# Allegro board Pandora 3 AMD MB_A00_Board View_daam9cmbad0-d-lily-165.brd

Outline 291.55 x 153.75 mm; copper layers: TOP, SGND, IN1, SVCC, IN2, IN3, SGND1, IN4, SGND2, BOTTOM. Coordinates in mm from the lower left corner of the outline.

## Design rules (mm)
net group DFP-S4(4.5: nets M_A_CLK0 M_A_CLK0# M_A_CLK1 M_A_CLK1# M_B_CLK0 M_B_CLK0# M_B_CLK1 M_B_CLK1#
net group DFP-S4.5(7: nets SATA_RXN0 SATA_RXN0_C SATA_RXP0 SATA_RXP0_C SATA_TXN0 SATA_TXN0_C SATA_TXP0 SATA_TXP0_C USB2_N1_L USB2_N1_R USB2_P1_L USB2_P1_R USB2N0 USB2N1_BT USB2N1_BT_R USB2N2_CAM USB2N2_CAM_R USB2N3_CR USB2N3_CR_R USB2P0 USB2P1_BT USB2P1_BT_R USB2P2_CAM USB2P2_CAM_R USB2P3_CR USB2P3_CR_R USB3_RXN2 USB3_RXN2_C USB3_RXN2_L USB3_RXN2_RE USB3_RXP2 USB3_RXP2_C USB3_RXP2_L USB3_RXP2_RE USB3_TXN2 USB3_TXN2_C USB3_TXN2_L USB3_TXN2_R USB3_TXN2_RE USB3_TXP2 USB3_TXP2_C USB3_TXP2_L USB3_TXP2_R USB3_TXP2_RE USB3_USB2_N2 USB3_USB2_P2
net group DFP-S4W4.5(4: nets CLK_PCIE_LANN CLK_PCIE_LANN_R CLK_PCIE_LANP CLK_PCIE_LANP_R CLK_PCIE_WLANN CLK_PCIE_WLANN_R CLK_PCIE_WLANP CLK_PCIE_WLANP_R CLK_VGA_N CLK_VGA_N_R CLK_VGA_P CLK_VGA_P_R EDP_AUXN EDP_AUXP EDP_TXN0 EDP_TXN1 EDP_TXP0 EDP_TXP1 INT_HDMI_TXCN INT_HDMI_TXCP INT_HDMI_TXN0 INT_HDMI_TXN1 INT_HDMI_TXN2 INT_HDMI_TXP0 INT_HDMI_TXP1 INT_HDMI_TXP2 PCIE_RXN0_WLAN PCIE_RXN1_LAN PCIE_RXN1_LAN_C PCIE_RXP0_WLAN PCIE_RXP1_LAN PCIE_RXP1_LAN_C PCIE_TXN0_WLAN PCIE_TXN0_WLAN_C PCIE_TXN1_LAN PCIE_TXN1_LAN_C PCIE_TXP0_WLAN PCIE_TXP0_WLAN_C PCIE_TXP1_LAN PCIE_TXP1_LAN_C PEG_RXN0 PEG_RXN0_C PEG_RXN1 PEG_RXN1_C PEG_RXN2 PEG_RXN2_C PEG_RXN3 PEG_RXN3_C PEG_RXN4 PEG_RXN4_C PEG_RXN5 PEG_RXN5_C PEG_RXN6 PEG_RXN6_C PEG_RXN7 PEG_RXN7_C PEG_RXP0 PEG_RXP0_C PEG_RXP1 PEG_RXP1_C PEG_RXP2 PEG_RXP2_C PEG_RXP3 PEG_RXP3_C PEG_RXP4 PEG_RXP4_C PEG_RXP5 PEG_RXP5_C PEG_RXP6 PEG_RXP6_C PEG_RXP7 PEG_RXP7_C PEG_TXN0_C PEG_TXN1_C PEG_TXN2 PEG_TXN2_C PEG_TXN3_C PEG_TXN4_C PEG_TXN5_C PEG_TXN6 PEG_TXN6_C PEG_TXN7_C PEG_TXP0_C PEG_TXP1_C PEG_TXP2 PEG_TXP2_C PEG_TXP3_C PEG_TXP4_C PEG_TXP5_C PEG_TXP6 PEG_TXP6_C PEG_TXP7_C SATA_RXN1 SATA_RXN1_C SATA_RXP1 SATA_RXP1_C SATA_TXN1 SATA_TXN1_C SATA_TXP1 SATA_TXP1_C USB3_RXN0 USB3_RXN0_C USB3_RXN0_L USB3_RXN1 USB3_RXN1_C USB3_RXN1_L USB3_RXP0 USB3_RXP0_C USB3_RXP0_L USB3_RXP1 USB3_RXP1_C USB3_RXP1_L USB3_TXN0 USB3_TXN0_C USB3_TXN0_L USB3_TXN0_RE USB3_TXN1 USB3_TXN1_C USB3_TXN1_L USB3_TXN1_RE USB3_TXP0 USB3_TXP0_C USB3_TXP0_L USB3_TXP0_RE USB3_TXP1 USB3_TXP1_C USB3_TXP1_L USB3_TXP1_RE USB3_USB2_N0 USB3_USB2_N1 USB3_USB2_P0 USB3_USB2_P1
net group DFP-S4W4.5-TB: nets EDP_AUXN_C EDP_AUXP_C EDP_TXN0_C EDP_TXN0_R EDP_TXN1_C EDP_TXN1_R EDP_TXP0_C EDP_TXP0_R EDP_TXP1_C EDP_TXP1_R HDMI_CLK+ HDMI_CLK- HDMI_TX0+ HDMI_TX0- HDMI_TX1+ HDMI_TX1- HDMI_TX2+ HDMI_TX2-
net group DFP-S4W5(4.5: nets M_A_DQS0 M_A_DQS1 M_A_DQS2 M_A_DQS3 M_A_DQS4 M_A_DQS5 M_A_DQS6 M_A_DQS7 M_A_DQS#0 M_A_DQS#1 M_A_DQS#2 M_A_DQS#3 M_A_DQS#4 M_A_DQS#5 M_A_DQS#6 M_A_DQS#7 M_B_DQS0 M_B_DQS1 M_B_DQS2 M_B_DQS3 M_B_DQS4 M_B_DQS5 M_B_DQS6 M_B_DQS7 M_B_DQS#0 M_B_DQS#1 M_B_DQS#2 M_B_DQS#3 M_B_DQS#4 M_B_DQS#5 M_B_DQS#6 M_B_DQS#7 WCKA0_0 WCKA0B_0 WCKA1_0 WCKA1B_0 WCKB1_1 WCKB1B_1
net group DFP-S8(7.5: nets LAN_MX0+ LAN_MX0- LAN_MX1+ LAN_MX1- LAN_MX2+ LAN_MX2- LAN_MX3+ LAN_MX3- MDI0+ MDI0- MDI1+ MDI1- MDI2- MDI3+ MDI3-
net group DFP-S8W4-TB: nets HDMI_CLK+_C HDMI_CLK+_R HDMI_CLK-_C HDMI_CLK-_R HDMI_TX0+_C HDMI_TX0+_R HDMI_TX0-_C HDMI_TX0-_R HDMI_TX1+_C HDMI_TX1+_R HDMI_TX1-_C HDMI_TX1-_R HDMI_TX2+_C HDMI_TX2+_R HDMI_TX2-_C HDMI_TX2-_R
net group DFP-S20W4.5-TB: nets 32K_X1 32K_X2 LAN_XTALO SI_XTALOUT XTALIN XTALOUT
net group W4.5(3.5: nets ACZ_BCLK_R ACZ_RST#_R ACZ_SDIN1 ACZ_SDIN2 ACZ_SDOUT_R ACZ_SPKR ACZ_SPKR_R ACZ_SYNC_R APU_PROCHOT#_R APU_PWRGD APU_SIC APU_SID APU_SPI_CLK APU_SPI_CS0# APU_SPI_HOLD# APU_SPI_SI APU_SPI_SO APU_SPI_WP BIOS_CS#_B BIOS_HOLD#_B BIOS_RD#_B BIOS_SPI_CLK_B BIOS_WP_B BIOS_WR#_B CLKRUN# CORE_PWM_PROCHOT# DGPUT_CLK DGPUT_CLK_R DGPUT_DATA DGPUT_DATA_R DMIC_CLK DMIC_CLK_C DMIC_CLK_R DMIC_DATA DMIC_DATA_C DMIC_DATA_R DP_AUX_ZVSS DP_ZVSS EC_SPI_CS# EC_SPI_DIN EC_SPI_DO EC_SPI_HOLD# EC_SPI_SCK EC_SPI_WP# GPIO_8_ROMSO GPIO_9_ROMSI GPIO_10_ROMSCK GPIO_22_ROMCSB HDA_BITCLK HDA_BITCLK_R HDA_RST# HDA_SDIN0 HDA_SDOUT HDA_SYNC HDMI_SCL HDMI_SCL_SNK HDMI_SDA HDMI_SDA_SNK I2C_SCL1 I2C_SCL_TP I2C_SDA1 I2C_SDA_TP LAD0 LAD0_R LAD1 LAD1_R LAD2 LAD2_R LAD3 LAD3_R LFRAME# LPC_LFRAME#_R ROMCSB ROMSCK ROMSI ROMSO SD_CD# SD_CLK SD_CMD SD_D0 SD_D1 SD_D2 SD_D3 SD_WP SERIRQ SMB_ALW_CLK SMB_ALW_DAT SMB_RUN_CLK SMB_RUN_DAT SMBCLK1 SMBCLK3 SMBDAT1 SMBDAT3
net group W4.5-TB: nets SL_CLK_100M
net group W5.5(4.5: nets ADBIA0 ADBIA1 ADBIB0 ADBIB1 CASA0B CASA1B CASB0B CASB1B CKEA0 CKEA1 CKEB0 CKEB1 CSA0B_0 CSA1B_0 CSB0B_0 CSB1B_0 DDBIA0_0 DDBIA0_1 DDBIA0_2 DDBIA0_3 DDBIA1_0 DDBIA1_1 DDBIA1_2 DDBIA1_3 DDBIB0_0 DDBIB0_1 DDBIB0_2 DDBIB0_3 DDBIB1_0 DDBIB1_1 DDBIB1_2 DDBIB1_3 DQA0_0 DQA0_1 DQA0_2 DQA0_3 DQA0_4 DQA0_5 DQA0_6 DQA0_7 DQA0_8 DQA0_9 DQA0_10 DQA0_11 DQA0_12 DQA0_13 DQA0_14 DQA0_15 DQA0_16 DQA0_17 DQA0_18 DQA0_19 DQA0_20 DQA0_21 DQA0_22 DQA0_23 DQA0_24 DQA0_25 DQA0_26 DQA0_27 DQA0_28 DQA0_29 DQA0_30 DQA0_31 DQA1_0 DQA1_1 DQA1_2 DQA1_3 DQA1_4 DQA1_5 DQA1_6 DQA1_7 DQA1_8 DQA1_9 DQA1_10 DQA1_11 DQA1_12 DQA1_13 DQA1_14 DQA1_15 DQA1_16 DQA1_17 DQA1_18 DQA1_19 DQA1_20 DQA1_21 DQA1_22 DQA1_23 DQA1_24 DQA1_25 DQA1_26 DQA1_27 DQA1_28 DQA1_29 DQA1_30 DQA1_31 DQB0_0 DQB0_1 DQB0_2 DQB0_3 DQB0_4 DQB0_5 DQB0_6 DQB0_7 DQB0_8 DQB0_9 DQB0_10 DQB0_11 DQB0_12 DQB0_13 DQB0_14 DQB0_15 DQB0_16 DQB0_17 DQB0_18 DQB0_19 DQB0_20 DQB0_21 DQB0_22 DQB0_23 DQB0_24 DQB0_25 DQB0_26 DQB0_27 DQB0_28 DQB0_29 DQB0_30 DQB0_31 DQB1_0 DQB1_1 DQB1_2 DQB1_3 DQB1_4 DQB1_5 DQB1_6 DQB1_7 DQB1_8 DQB1_9 DQB1_10 DQB1_11 DQB1_12 DQB1_13 DQB1_14 DQB1_15 DQB1_16 DQB1_17 DQB1_18 DQB1_19 DQB1_20 DQB1_21 DQB1_22 DQB1_23 DQB1_24 DQB1_25 DQB1_26 DQB1_27 DQB1_28 DQB1_29 DQB1_30 DQB1_31 EDCA0_0 EDCA0_1 EDCA0_2 EDCA0_3 EDCA1_0 EDCA1_1 EDCA1_2 EDCA1_3 EDCB0_0 EDCB0_1 EDCB0_2 EDCB0_3 EDCB1_0 EDCB1_1 EDCB1_2 EDCB1_3 MAA0_0 MAA0_1 MAA0_2 MAA0_3 MAA0_4 MAA0_5 MAA0_6 MAA0_7 MAA0_8 MAA1_0 MAA1_1 MAA1_2 MAA1_3 MAA1_4 MAA1_5 MAA1_6 MAA1_7 MAA1_8 MAB0_0 MAB0_1 MAB0_2 MAB0_3 MAB0_4 MAB0_5 MAB0_6 MAB0_7 MAB0_8 MAB1_0 MAB1_1 MAB1_2 MAB1_3 MAB1_4 MAB1_5 MAB1_6 MAB1_7 MAB1_8 RASA0B RASA1B RASB0B RASB1B WEA0B WEA1B WEB0B WEB1B
net group W7(5: nets M_A_A0 M_A_A1 M_A_A2 M_A_A3 M_A_A4 M_A_A5 M_A_A6 M_A_A7 M_A_A8 M_A_A9 M_A_A10 M_A_A11 M_A_A12 M_A_A13 M_A_BS#0 M_A_BS#1 M_A_CAS# M_A_CKE0 M_A_CKE1 M_A_DM0 M_A_DM1 M_A_DM2 M_A_DM3 M_A_DM4 M_A_DM5 M_A_DM6 M_A_DM7 M_A_DQ0 M_A_DQ1 M_A_DQ2 M_A_DQ3 M_A_DQ4 M_A_DQ5 M_A_DQ6 M_A_DQ7 M_A_DQ8 M_A_DQ9 M_A_DQ10 M_A_DQ11 M_A_DQ12 M_A_DQ13 M_A_DQ14 M_A_DQ15 M_A_DQ16 M_A_DQ17 M_A_DQ18 M_A_DQ19 M_A_DQ20 M_A_DQ21 M_A_DQ22 M_A_DQ23 M_A_DQ24 M_A_DQ25 M_A_DQ26 M_A_DQ27 M_A_DQ28 M_A_DQ29 M_A_DQ30 M_A_DQ31 M_A_DQ32 M_A_DQ33 M_A_DQ34 M_A_DQ35 M_A_DQ36 M_A_DQ37 M_A_DQ38 M_A_DQ39 M_A_DQ40 M_A_DQ41 M_A_DQ42 M_A_DQ43 M_A_DQ44 M_A_DQ45 M_A_DQ46 M_A_DQ47 M_A_DQ48 M_A_DQ49 M_A_DQ50 M_A_DQ51 M_A_DQ52 M_A_DQ53 M_A_DQ54 M_A_DQ55 M_A_DQ56 M_A_DQ57 M_A_DQ58 M_A_DQ59 M_A_DQ60 M_A_DQ61 M_A_DQ62 M_A_DQ63 M_A_EVENT# M_A_ODT0 M_A_ODT1 M_A_RAS# M_A_RESET# M_A_WE# M_B0_ODT0 M_B0_ODT1 M_B_A0 M_B_A1 M_B_A2 M_B_A3 M_B_A4 M_B_A5 M_B_A6 M_B_A7 M_B_A8 M_B_A9 M_B_A10 M_B_A11 M_B_A12 M_B_A13 M_B_BS#0 M_B_BS#1 M_B_CAS# M_B_CKE0 M_B_CKE1 M_B_DM0 M_B_DM1 M_B_DM2 M_B_DM3 M_B_DM4 M_B_DM5 M_B_DM6 M_B_DM7 M_B_DQ0 M_B_DQ1 M_B_DQ2 M_B_DQ3 M_B_DQ4 M_B_DQ5 M_B_DQ6 M_B_DQ7 M_B_DQ8 M_B_DQ9 M_B_DQ10 M_B_DQ11 M_B_DQ12 M_B_DQ13 M_B_DQ14 M_B_DQ15 M_B_DQ16 M_B_DQ17 M_B_DQ18 M_B_DQ19 M_B_DQ20 M_B_DQ21 M_B_DQ22 M_B_DQ23 M_B_DQ24 M_B_DQ25 M_B_DQ26 M_B_DQ27 M_B_DQ28 M_B_DQ29 M_B_DQ30 M_B_DQ31 M_B_DQ32 M_B_DQ33 M_B_DQ34 M_B_DQ35 M_B_DQ36 M_B_DQ37 M_B_DQ38 M_B_DQ39 M_B_DQ40 M_B_DQ41 M_B_DQ42 M_B_DQ43 M_B_DQ44 M_B_DQ45 M_B_DQ46 M_B_DQ47 M_B_DQ48 M_B_DQ49 M_B_DQ50 M_B_DQ51 M_B_DQ52 M_B_DQ53 M_B_DQ54 M_B_DQ55 M_B_DQ56 M_B_DQ57 M_B_DQ58 M_B_DQ59 M_B_DQ60 M_B_DQ61 M_B_DQ62 M_B_DQ63 M_B_EVENT# M_B_RAS# M_B_RESET# M_B_WE# M_MA_BG0 M_MA_BG1 M_MB_BG0 M_MB_BG1 MEM_MA_ACT# MEM_MB_ACT#
net group W10-T1234B: nets 62771_SVC 62771_SVC_GFX 62771_SVD 62771_SVD_GFX 62771_SVT 62771_SVT_GFX APU_SVC APU_SVD APU_SVT GFX_SVC GFX_SVC_R GFX_SVD GFX_SVD_R GFX_SVT P_ZVDDP_P_TX_095 P_ZVSS_P_RX_095 SVC SVD
net group W40-T1234B: nets AUD_SPK_L+ AUD_SPK_L- AUD_SPK_R+ AUD_SPK_R-

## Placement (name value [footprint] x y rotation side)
C8  0.22U/10V_4  [C0402]  62.94 124.59 90 bottom
C9  0.22U/10V_4  [C0402]  61.98 124.59 90 bottom
C10  0.22U/10V_4  [C0402]  60.31 122.45 90 bottom
C11  0.22U/10V_4  [C0402]  61.32 122.45 90 bottom
C12  0.22U/10V_4  [C0402]  58.51 123.12 180 bottom
C13  0.22U/10V_4  [C0402]  58.51 124.13 180 bottom
C14  0.22U/10V_4  [C0402]  54.7 122.35 180 bottom
C15  0.22U/10V_4  [C0402]  54.7 123.37 180 bottom
C16  0.22U/10V_4  [C0402]  50.91 123.42 180 bottom
C17  0.22U/10V_4  [C0402]  50.91 122.41 180 bottom
C18  0.22U/10V_4  [C0402]  50.89 120.25 180 bottom
C19  0.22U/10V_4  [C0402]  50.89 121.27 180 bottom
C20  0.22U/10V_4  [C0402]  50.87 119.12 180 bottom
C21  0.22U/10V_4  [C0402]  50.87 118.11 180 bottom
C22  0.22U/10V_4  [C0402]  50.86 117.13 180 bottom
C23  0.22U/10V_4  [C0402]  50.86 116.17 180 bottom
C199  *MLVG04021R0UV18BP_NC  [C0402]  268.42 108.01 270 top
C215  *MLVG04021R0UV18BP_NC  [C0402]  268.42 106.29 90 top
C225  *2200P/50V_4_NC  [C0402]  69.44 102.58 180 top
C228  0.1U/16V/X7R_4  [C0402]  267.9 104.95 0 top
C254  *MLVG04021R0UV18BP_NC  [C0402]  268.42 103.61 270 top
C287  *MLVG04021R0UV18BP_NC  [C0402]  268.42 101.58 90 top
C302  *MLVG04021R0UV18BP_NC  [C0402]  267.4 99.55 270 top
C310  *MLVG04021R0UV18BP_NC  [C0402]  267.4 97.52 90 top
C323  *MLVG04021R0UV18BP_NC  [C0402]  268.42 95.48 270 top
C334  4.7U/6.3V_6  [C0603]  38.67 91.9 180 top
C336  *MLVG04021R0UV18BP_NC  [C0402]  267.4 93.45 90 top
C339  0.1U/16V/X7R_4  [C0402]  38.57 90.48 0 top
C341  *4.7U/6.3V_6_NC  [C0603]  276.01 91.72 180 top
C343  0.1U/16V/X7R_4  [C0402]  273.22 88.93 0 bottom
C345  10P/50V_4  [C0402]  275.4 89.03 270 top
C347  10P/50V_4  [C0402]  275.4 87.2 90 top
C352  0.1U/16V/X7R_4  [C0402]  274.64 84.82 0 top
C356  0.1U/16V/X7R_4  [C0402]  271.56 86.42 90 bottom
C357  1U/6.3V_4  [C0402]  270.52 86.42 90 bottom
C359  *4.7U/6.3V_6_NC  [C0603]  272.76 90.73 90 bottom
C360  *0.1U/16V/X7R_4_NC  [C0402]  275.76 81.97 0 top
C370  0.1U/16V/X7R_4  [C0402]  173.5 80.53 180 top
C371  4.7U/6.3V_6  [C0603]  172.63 79.3 0 top
C391  0.1U/16V/X7R_4  [C0402]  276.57 70.11 90 top
C413  0.01U/50V/X7R_4  [C0402]  266.82 65.45 270 top
C414  0.1U/16V/X7R_4  [C0402]  265.93 64.11 180 top
C415  0.01U/50V/X7R_4  [C0402]  275.56 64.83 90 top
C418  0.1U/16V/X7R_4  [C0402]  267.7 61.47 270 top
C419  0.1U/16V/X7R_4  [C0402]  268.72 61.47 270 top
C420  0.1U/16V/X7R_4  [C0402]  269.81 61.47 270 top
C421  0.1U/16V/X7R_4  [C0402]  270.82 61.47 270 top
C422  0.1U/16V/X7R_4  [C0402]  271.84 61.47 270 top
C423  0.1U/16V/X7R_4  [C0402]  272.86 61.47 270 top
C424  0.1U/16V/X7R_4  [C0402]  273.87 61.47 270 top
C425  0.1U/16V/X7R_4  [C0402]  274.89 61.47 270 top
C458  0.1U/16V/X7R_4  [C0402]  173.38 52.3 180 top
C459  0.1U/16V/X7R_4  [C0402]  171.87 53.7 270 top
C463  0.1U/25V_6  [C0603]  182.82 51.67 270 top
C464  0.1U/25V_6  [C0603]  184.34 51.67 270 top
C478  0.01U/50V/X7R_4  [C0402]  168.49 49.34 0 top
C479  0.1U/16V/X7R_4  [C0402]  170.46 49.32 180 top
C481  10U/6.3V_6  [C0603]  273.09 46.89 90 top
C482  0.1U/16V/X7R_4  [C0402]  271.9 46.94 90 top
C483  150P/50V_4  [C0402]  270.94 46.94 90 top
C485  1U/25V_6  [C0603]  179.64 43.79 0 top
C486  *0.1U/16V/X7R_4_NC  [C0402]  184.98 43.92 180 top
C487  *100P/50V_4_NC  [C0402]  270.37 43.64 0 top
C489  0.1U/25V_6  [C0603]  183.05 42.93 90 top
C490  *100P/50V_4_NC  [C0402]  270.34 42.07 0 top
C496  *4.7U/6.3V_6_NC  [C0603]  263.06 41.84 180 top
C497  0.1U/16V/X7R_4  [C0402]  263 43.03 180 top
C502  0.1U/16V/X7R_4  [C0402]  106.79 36.4 180 top
C503  0.1U/16V/X7R_4  [C0402]  171.51 35.67 270 top
C504  0.1U/16V/X7R_4  [C0402]  172.53 35.67 270 top
C509  0.1U/16V_4  [C0402]  171.64 34.24 0 bottom
C512  0.1U/16V/X7R_4  [C0402]  13.11 29.36 90 top
C513  1U/6.3V_4  [C0402]  14.1 29.36 90 top
C517  0.1U/16V/X7R_4  [C0402]  250.47 25.46 180 top
C526  0.047U/10V_4  [C0402]  6.52 18.42 180 top
C529  0.1U/16V/X7R_4  [C0402]  5.96 4.2 180 top
C530  0.1U/16V/X7R_4  [C0402]  25.57 3.29 90 top
C531  1U/6.3V_4  [C0402]  24.45 3.29 90 top
C533  0.047U/10V_4  [C0402]  5.96 3.1 180 top
C573  0.1U/16V/X7R_4  [C0402]  42.86 110.34 180 top
C574  2200P/50V_4  [C0402]  43.5 113.77 180 bottom
C593  1000P/3KV_18  [CC1808]  277.43 110.98 0 bottom
C623  0.1U/25V_6  [C0603]  104.76 15.58 270 bottom
C624  *0.1U/16V/X7R_4_NC  [C0402]  271.5 83.15 270 top
C625  0.1U/16V/X7R_4  [C0402]  271.16 90.45 90 bottom
C626  0.1U/16V/X7R_4  [C0402]  270.12 90.45 90 bottom
C627  0.1U/16V/X7R_4  [C0402]  275.04 90.53 180 top
C628  0.1U/16V/X7R_4  [C0402]  268.77 89.64 0 bottom
C632  *4.7U/6.3V_6_NC  [C0603]  268.67 88.17 0 bottom
C634  0.1U/16V_4  [C0402]  272.66 82.61 180 bottom
C635  *4.7U/6.3V_6_NC  [C0603]  272.68 83.27 90 top
C638  1U/6.3V_4  [C0402]  272.71 80.35 180 bottom
C642  0.1U/16V/X7R_4  [C0402]  267.16 74.55 270 top
C643  0.1U/16V/X7R_4  [C0402]  268.18 74.55 270 top
C645  0.1U/16V/X7R_4  [C0402]  273.22 87.94 0 bottom
C648  0.01U/50V/X7R_4  [C0402]  277.74 82.91 90 bottom
C659  0.01U/50V/X7R_4  [C0402]  268.5 70.7 90 top
C660  1U/6.3V_4  [C0402]  265.93 63.15 0 top
C661  0.1U/16V/X7R_4  [C0402]  275.07 68.94 270 top
C662  0.1U/16V/X7R_4  [C0402]  275.08 70.7 90 top
C663  0.1U/16V/X7R_4  [C0402]  267.54 70.98 90 top
C664  0.1U/16V/X7R_4  [C0402]  276.83 63.31 90 top
C665  0.1U/25V_6  [C0603]  103.32 15.58 270 bottom
C666  0.1U/16V/X7R_4  [C0402]  175.96 57.76 270 bottom
C667  0.1U/16V/X7R_4  [C0402]  176.98 57.76 270 bottom
C668  0.1U/16V/X7R_4  [C0402]  178.25 57.76 270 bottom
C669  0.1U/16V/X7R_4  [C0402]  179.26 57.76 270 bottom
C674  0.1U/16V/X7R_4  [C0402]  172.89 53.7 270 top
C675  0.1U/16V/X7R_4  [C0402]  173.67 54.08 270 bottom
C676  0.1U/16V/X7R_4  [C0402]  174.82 54.08 270 bottom
C681  0.047U/25V_4  [C0402]  264.99 55.99 90 bottom
C682  0.1U/25V_6  [C0603]  101.13 16.16 0 bottom
C684  *10U/6.3V_6_NC  [C0603]  263 46.89 0 top
C688  *100P/50V_4_NC  [C0402]  268.49 41.3 180 top
C689  0.022U/25V_4  [C0402]  177.51 36.35 270 bottom
C690  0.1U/25V_6  [C0603]  83.5 5.44 90 bottom
C691  0.1U/16V/X7R_4  [C0402]  236.97 24.42 180 bottom
C692  0.1U/16V_4  [C0402]  194.5 30.08 180 bottom
C694  10U/6.3V_6  [C0603]  194.76 28.81 0 bottom
C700  0.1U/16V/X7R_4  [C0402]  5.75 25.13 270 bottom
C701  4.7U/6.3V_6  [C0603]  4.48 25.13 270 bottom
C703  *68P/50V_4_NC  [C0402]  194.5 25.25 180 bottom
C712  0.1U/16V/X7R_4  [C0402]  230.82 19.64 180 bottom
C714  *0.1U/16V/X7R_4_NC  [C0402]  224.7 17.45 90 bottom
C716  *0.1U/16V/X7R_4_NC  [C0402]  230.32 18.09 270 bottom
C723  10U/6.3V_6  [C0603]  194.88 15.6 0 bottom
C724  0.1U/16V/X7R_4  [C0402]  57.59 16.57 270 bottom
C725  0.01U/50V/X7R_4  [C0402]  232.86 14.71 0 bottom
C728  0.1U/16V/X7R_4  [C0402]  224.98 14.08 90 bottom
C729  0.1U/16V_4  [C0402]  194.63 14.33 180 bottom
C730  0.1U/16V_4  [C0402]  194.63 13.19 180 bottom
C733  0.1U/16V_4  [C0402]  194.63 12.04 180 bottom
C734  0.1U/16V/X7R_4  [C0402]  29.91 9.76 180 bottom
C735  4.7U/6.3V_6  [C0603]  27.12 11.28 0 bottom
C739  0.01U/50V/X7R_4  [C0402]  33.21 9.94 270 bottom
C740  0.01U/50V/X7R_4  [C0402]  34.3 9.94 270 bottom
C741  0.01U/50V/X7R_4  [C0402]  35.32 9.94 270 bottom
C742  0.01U/50V/X7R_4  [C0402]  36.46 9.94 270 bottom
C743  *22U/6.3V_6_NC  [C0603]  30.42 11.28 180 bottom
C744  4.7U/6.3V_6  [C0603]  27.12 9.76 0 bottom
C745  0.1U/16V/X7R_4  [C0402]  21.84 8.03 0 bottom
C746  0.1U/16V/X7R_4  [C0402]  20.41 6.9 90 bottom
C747  0.1U/25V_6  [C0603]  150.25 31.6 180 bottom
C748  0.1U/25V_6  [C0603]  150.25 33.13 180 bottom
C749  0.1U/16V_4  [C0402]  63.9 124.59 270 bottom
C750  0.1U/16V_4  [C0402]  64.86 124.59 270 bottom
C751  *150P/50V_4_NC  [C0402]  57.27 104.81 180 top
C752  *150P/50V_4_NC  [C0402]  50.86 102.46 0 bottom
C753  0.1U/16V_4  [C0402]  51.96 22.89 270 top
C754  0.01u/50V_4  [C0402]  38.8 25 180 top
C755  *0.01U/50V_4_NC  [C0402]  51.5 26.14 180 top
C756  0.01u/50V_4  [C0402]  49.47 20.66 0 top
C757  150P/50V_4  [C0402]  97.98 109.68 0 bottom
C758  150P/50V_4  [C0402]  103.94 104.86 90 top
C759  *0.1u/16V_4_NC  [C0402]  102.92 104.86 270 top
C760  0.1U/16V_4  [C0402]  99.68 112.13 180 top
C761  *100P/50V_4_NC  [C0402]  80.73 120.93 90 bottom
C762  18P/50V_4  [C0402]  103.46 116.89 180 top
C763  18P/50V_4  [C0402]  100.02 116.89 0 top
C764  *0.22U/10V_4_NC  [C0402]  88.33 124.9 180 bottom
C766  4.7P/50V_4  [C0402]  68.88 121.52 180 bottom
C767  4.7P/50V_4  [C0402]  67.16 121.52 180 bottom
C768  10P/50V_4  [C0402]  102.81 107.27 0 bottom
C769  *10P/50V_4_NC  [C0402]  102.68 108.67 0 bottom
C770  *0.1u/16V_4_NC  [C0402]  123.89 144.51 0 top
C771  22U/6.3V/X5R_6  [C0603]  83.48 91.5 180 top
C772  22U/6.3V/X5R_6  [C0603]  83.48 90.09 180 top
C773  22U/6.3V/X5R_6  [C0603]  65.35 91.42 180 top
C774  22U/6.3V/X5R_6  [C0603]  80.97 91.98 270 top
C775  22U/6.3V/X5R_6  [C0603]  70.29 90.25 270 top
C776  47U/4V/X5R_6  [C0603]  77.05 99.09 90 top
C777  22U/6.3V/X5R_6  [C0603]  69.79 98.25 0 top
C779  22U/6.3V/X5R_6  [C0603]  80.33 132.75 270 bottom
C782  0.22U/10V_4  [C0402]  71.3 96.4 270 top
C783  0.22U/10V_4  [C0402]  64.75 94.26 0 top
C784  0.22U/10V_4  [C0402]  65.12 92.64 180 top
C785  22U/6.3V/X5R_6  [C0603]  62.53 93.38 0 top
C786  22U/6.3V/X5R_6  [C0603]  62.5 95.86 0 top
C787  22U/6.3V/X5R_6  [C0603]  75.86 92.25 180 top
C788  22U/6.3V/X5R_6  [C0603]  75.86 90.84 180 top
C789  22U/6.3V/X5R_6  [C0603]  78.51 90.63 0 top
C790  22U/6.3V/X5R_6  [C0603]  66.89 89.29 0 top
C792  47U/4V/X5R_6  [C0603]  70.3 108.72 0 top
C793  47U/4V/X5R_6  [C0603]  70.3 107.16 0 top
C798  0.22U/10V_4  [C0402]  68.15 90.85 270 top
C799  0.22U/10V_4  [C0402]  63.18 91.43 0 top
C800  0.22U/10V_4  [C0402]  67.19 90.85 270 top
C801  180P/50V_4  [C0402]  67.65 93.42 90 top
C802  0.22U/10V_4  [C0402]  71.1 102.2 270 top
C803  0.22U/10V_4  [C0402]  75.49 109.23 180 top
C804  0.22U/10V_4  [C0402]  70.05 111.45 270 top
C805  0.22U/10V_4  [C0402]  71.37 113.18 270 top
C806  0.22U/10V_4  [C0402]  72.62 110.96 90 top
C807  0.22U/10V_4  [C0402]  72.9 109.4 0 top
C808  0.22U/10V_4  [C0402]  69.44 101.62 0 top
C809  0.22U/10V_4  [C0402]  77.37 111.62 90 top
C810  180P/50V_4  [C0402]  79.59 111.68 90 top
C811  0.22U/10V_4  [C0402]  71.5 89.97 270 top
C812  0.22U/10V_4  [C0402]  69.11 90.92 270 top
C813  0.22U/10V_4  [C0402]  71.37 92.79 90 top
C814  0.22U/10V_4  [C0402]  74.16 94.2 0 top
C815  180P/50V_4  [C0402]  71.96 91.38 0 top
C816  180P/50V_4  [C0402]  79.53 92.19 270 top
C817  10U/6.3V_4  [C0402]  101.91 102.04 0 top
C818  0.22U/10V_4  [C0402]  101.91 103.05 0 top
C819  10U/6.3V_4  [C0402]  99 100.69 270 top
C820  10U/6.3V_4  [C0402]  104.33 98.79 90 top
C821  10U/6.3V_4  [C0402]  84.29 101.1 0 top
C822  10U/6.3V_4  [C0402]  86.55 101.05 180 top
C823  0.22U/10V_4  [C0402]  102.3 98.79 90 top
C824  0.22U/10V_4  [C0402]  100.14 100.69 270 top
C825  0.22U/10V_4  [C0402]  101.28 100.69 270 top
C826  0.22U/10V_4  [C0402]  103.32 98.79 90 top
C827  0.22U/10V_4  [C0402]  99 98.79 90 top
C828  0.22U/10V_4  [C0402]  100.14 98.79 90 top
C829  180P/50V_4  [C0402]  101.28 98.79 90 top
C830  1U/6.3V_4  [C0402]  89.69 100.77 90 top
C831  1U/6.3V_4  [C0402]  87.32 99.86 180 top
C832  1U/6.3V_4  [C0402]  88.73 100.77 90 top
C833  22U/6.3V/X5R_6  [C0603]  55.88 103.5 0 top
C834  22U/6.3V/X5R_6  [C0603]  56.11 110.9 0 top
C835  22U/6.3V/X5R_6  [C0603]  64.24 115.31 180 top
C836  22U/6.3V/X5R_6  [C0603]  63.16 107.5 270 top
C837  22U/6.3V/X5R_6  [C0603]  60.91 108.89 90 top
C838  22U/6.3V/X5R_6  [C0603]  63.16 102.21 270 top
C839  22U/6.3V/X5R_6  [C0603]  63.16 104.88 90 top
C840  22U/6.3V/X5R_6  [C0603]  60.74 115.31 0 top
C841  22U/6.3V/X5R_6  [C0603]  63.83 111.89 270 top
C842  10U/6.3V_4  [C0402]  85.83 108.41 270 top
C843  10U/6.3V_4  [C0402]  86.84 108.41 270 top
C844  0.22U/10V_4  [C0402]  84.81 108.41 270 top
C845  0.22U/10V_4  [C0402]  58.99 104.77 0 top
C846  0.22U/10V_4  [C0402]  62.13 99.95 90 top
C847  0.22U/10V_4  [C0402]  65.28 112.03 270 top
C848  0.22U/10V_4  [C0402]  61.64 113.49 270 top
C849  0.22U/10V_4  [C0402]  63.38 99.92 90 top
C850  0.22U/10V_4  [C0402]  66.53 112.1 270 top
C851  0.22U/10V_4  [C0402]  55.65 99.88 90 top
C852  0.22U/10V_4  [C0402]  57.77 100.31 90 top
C853  0.22U/10V_4  [C0402]  59.3 105.76 0 top
C854  180P/50V_4  [C0402]  68.23 110.44 180 top
C860  22U/6.3V/X5R_6  [C0603]  96.84 125.64 0 bottom
C862  22U/6.3V/X5R_6  [C0603]  96.84 127.05 0 bottom
C863  47U/4V/X5R_6  [C0603]  79.36 105.14 0 top
C864  0.22U/10V_4  [C0402]  78.62 98.93 0 top
C865  0.22U/10V_4  [C0402]  79.87 108.62 270 top
C866  0.22U/10V_4  [C0402]  78.59 101.99 90 top
C867  0.22U/10V_4  [C0402]  79.57 100.27 90 top
C868  0.22U/10V_4  [C0402]  78.61 100.27 90 top
C869  0.22U/10V_4  [C0402]  82.23 100.28 90 top
C870  0.22U/10V_4  [C0402]  78.62 97.97 0 top
C871  0.22U/10V_4  [C0402]  81.72 102.24 270 top
C872  180P/50V_4  [C0402]  79.57 101.99 90 top
C873  0.22U/10V_4  [C0402]  83.32 102.48 90 top
C874  10U/6.3V_4  [C0402]  241.72 9.48 90 top
C875  1U/6.3V_4  [C0402]  105.44 108.43 90 top
C876  0.1U/16V_4  [C0402]  243.9 6.66 0 top
C877  1U/6.3V_4  [C0402]  269.23 3 0 top
C878  10U/6.3V_4  [C0402]  82.68 104.26 270 top
C879  0.22U/10V_4  [C0402]  81.72 104.26 270 top
C880  10U/6.3V_4  [C0402]  88.31 109.82 270 top
C881  0.22U/10V_4  [C0402]  89.27 109.82 270 top
C882  10U/6.3V_4  [C0402]  89.06 99.42 180 top
C883  10U/6.3V_4  [C0402]  81.97 106.31 270 top
C884  0.22U/10V_4  [C0402]  84.93 105.01 270 top
C885  10U/6.3V_4  [C0402]  81.89 109.96 0 top
C886  0.22U/10V_4  [C0402]  81.07 108.62 270 top
C887  1U/6.3V_4  [C0402]  29.62 55.55 0 bottom
C888  1000p/50V_4  [C0402]  84.14 44.73 270 top
C889  1U/6.3V_4  [C0402]  106.97 53.22 90 top
C890  0.1u/16V_4  [C0402]  76.16 46.93 0 top
C891  0.1u/16V_4  [C0402]  73.34 53.13 270 top
C892  0.1u/16V_4  [C0402]  77.28 50.1 90 top
C893  0.1u/16V_4  [C0402]  74.39 53.13 270 top
C894  0.1u/16V_4  [C0402]  72.31 53.13 270 top
C895  0.1u/16V_4  [C0402]  75.9 50.05 90 top
C896  4.7U/6.3V_4  [C0402]  109.43 45.39 180 top
C897  0.1u/16V_4  [C0402]  109.43 44.43 180 top
C898  0.1u/16V_4  [C0402]  85.15 44.73 90 top
C899  0.1u/16V_4  [C0402]  87.19 44.73 90 top
C900  0.1u/16V_4  [C0402]  78.18 47.65 270 top
C901  0.1u/16V_4  [C0402]  74.22 51.19 180 top
C902  0.1u/16V_4  [C0402]  71.29 53.13 270 top
C903  0.1u/16V_4  [C0402]  70.45 50.38 90 top
C904  0.1u/16V_4  [C0402]  72.14 48.93 0 top
C905  0.1u/16V_4  [C0402]  64.21 48.89 0 top
C906  180P/50V_4  [C0402]  107.4 51.34 270 top
C907  0.1u/16V_4  [C0402]  108.77 51.97 0 top
C908  0.1u/16V_4  [C0402]  108.77 52.98 0 top
C909  180P/50V_4  [C0402]  80.48 52.56 180 top
C910  22U/6.3V_6  [C0603]  69.19 45.21 0 top
C911  22U/6.3V_6  [C0603]  79.94 46.24 270 top
C912  22U/6.3V_6  [C0603]  69.92 47.91 270 top
C913  22U/6.3V_6  [C0603]  74.29 45.32 180 top
C914  22U/6.3V_6  [C0603]  79.85 49.62 90 top
C915  22U/6.3V_6  [C0603]  74.61 49.28 270 top
C916  22U/6.3V_6  [C0603]  63.86 50.08 0 top
C917  1U/6.3V_4  [C0402]  104.94 64.81 270 top
C918  1000p/50V_4  [C0402]  83.14 54.98 270 top
C919  1U/6.3V_4  [C0402]  105.91 66.3 180 top
C920  0.1u/16V_4  [C0402]  81.53 63.79 180 top
C921  0.1u/16V_4  [C0402]  75.17 61.88 90 top
C922  0.1u/16V_4  [C0402]  74.05 61.24 90 top
C923  0.1u/16V_4  [C0402]  69.78 60.5 270 top
C924  0.1u/16V_4  [C0402]  71.19 60.72 270 top
C925  0.1u/16V_4  [C0402]  76.39 63.63 270 top
C926  4.7U/6.3V_4  [C0402]  106.83 57.38 270 top
C927  0.1u/16V_4  [C0402]  107.85 57.38 270 top
C928  0.1u/16V_4  [C0402]  82.12 54.98 90 top
C929  0.1u/16V_4  [C0402]  86.42 54.99 90 top
C930  0.1u/16V_4  [C0402]  68.72 63.17 90 top
C931  0.1u/16V_4  [C0402]  76.28 61.86 90 top
C932  0.1u/16V_4  [C0402]  72.18 60.7 270 top
C933  0.1u/16V_4  [C0402]  70.4 63.17 90 top
C934  0.1u/16V_4  [C0402]  81.41 61.46 180 top
C935  0.1u/16V_4  [C0402]  67.1 63.63 90 top
C936  180P/50V_4  [C0402]  106.82 68.83 180 bottom
C937  0.1u/16V_4  [C0402]  106.82 67.82 180 bottom
C938  0.1u/16V_4  [C0402]  106.82 69.85 180 bottom
C939  180P/50V_4  [C0402]  81.41 62.46 180 top
C940  22U/6.3V_6  [C0603]  69.11 57.16 90 top
C941  22U/6.3V_6  [C0603]  70.52 57.16 90 top
C942  22U/6.3V_6  [C0603]  72.73 63.04 90 top
C943  22U/6.3V_6  [C0603]  81.85 58.78 180 top
C944  22U/6.3V_6  [C0603]  74.95 65.28 180 top
C945  22U/6.3V_6  [C0603]  75.94 59.68 270 top
C946  22U/6.3V_6  [C0603]  65.32 63.49 90 top
C947  0.22U/10V_4  [C0402]  121.19 93.33 180 top
C948  0.22U/10V_4  [C0402]  121.19 94.35 180 top
C949  0.22U/10V_4  [C0402]  118.65 94.35 180 top
C950  0.22U/10V_4  [C0402]  118.65 93.33 180 top
C951  0.22U/10V_4  [C0402]  121.19 97.02 180 top
C952  0.22U/10V_4  [C0402]  121.19 96 180 top
C953  0.22U/10V_4  [C0402]  118.52 97.27 180 top
C954  0.22U/10V_4  [C0402]  118.52 96.25 180 top
C955  0.22U/10V_4  [C0402]  121.06 99.56 180 top
C956  0.22U/10V_4  [C0402]  121.06 98.54 180 top
C957  0.22U/10V_4  [C0402]  118.39 99.68 180 top
C958  0.22U/10V_4  [C0402]  118.39 100.7 180 top
C959  0.22U/10V_4  [C0402]  121.19 102.1 180 top
C960  0.22U/10V_4  [C0402]  121.19 101.08 180 top
C961  0.22U/10V_4  [C0402]  117.81 103.26 180 top
C962  0.22U/10V_4  [C0402]  117.81 102.25 180 top
C964  *0.1U/16V_4_X7R_NC  [C0402]  123 87.1 180 bottom
C965  *0.1U/16V_4_X7R_NC  [C0402]  116.78 88.24 0 bottom
C968  120P/50V_4  [C0402]  122.11 111.74 0 bottom
C969  120P/50V_4  [C0402]  149.1 84.74 270 bottom
C970  1U/6.3V_4  [C0402]  140.71 93.58 90 top
C971  *1U/6.3V_4_NC  [C0402]  145.99 84.74 270 bottom
C973  *1U/6.3V_4_NC  [C0402]  145.03 86.85 270 bottom
C974  1U/6.3V_4  [C0402]  144.75 84.61 90 bottom
C977  12P/50V_4  [C0402]  116.02 84.31 270 bottom
C978  12P/50V_4  [C0402]  116.02 80.37 90 bottom
C979  0.1U/16V_4  [C0402]  121.1 80.5 0 bottom
C980  1U/6.3V_4  [C0402]  154.6 73.61 90 top
C981  1U/6.3V_4  [C0402]  148.93 79.94 270 bottom
C982  1U/6.3V_4  [C0402]  136.81 100.06 180 top
C983  1U/6.3V_4  [C0402]  155.59 73.61 90 top
C984  1U/6.3V_4  [C0402]  139.86 97.12 180 top
C985  1U/6.3V_4  [C0402]  126.25 74.7 90 top
C986  1U/6.3V_4  [C0402]  141.12 75.16 90 top
C987  1U/6.3V_4  [C0402]  134.38 102.73 90 top
C988  1U/6.3V_4  [C0402]  137.2 98.71 270 top
C989  1U/6.3V_4  [C0402]  128.79 81.2 270 top
C990  1U/6.3V_4  [C0402]  149.99 79.95 270 bottom
C991  22U/6.3V_6  [C0603]  149.03 80.63 90 top
C992  22U/6.3V_6  [C0603]  134.58 94.8 270 top
C993  22U/6.3V_6  [C0603]  130.03 81.53 90 top
C994  22U/6.3V_6  [C0603]  142.45 75.6 270 top
C995  47U/4V/X5R_6  [C0603]  143.69 98.95 270 top
C996  22U/6.3V_6  [C0603]  143.03 101.46 180 top
C997  47U/4V/X5R_6  [C0603]  142.06 99.05 270 top
C998  22U/6.3V_6  [C0603]  131.55 81.53 90 top
C999  22U/6.3V_6  [C0603]  143.41 103.44 0 top
C1000  22U/6.3V_6  [C0603]  136.81 102.1 270 top
C1001  330U_2.5V_3528  [C3528]  139.64 101.58 270 top
C1002  1U/6.3V_4  [C0402]  145.89 102.23 0 top
C1003  1U/6.3V_4  [C0402]  147.94 102.4 180 top
C1004  1U/6.3V_4  [C0402]  133.29 108.82 0 top
C1005  1U/6.3V_4  [C0402]  145.24 106.69 180 top
C1006  1U/6.3V_4  [C0402]  145.05 97.39 270 top
C1007  1U/6.3V_4  [C0402]  146.31 96.76 270 top
C1008  1U/6.3V_4  [C0402]  143.6 94.98 270 top
C1009  22U/6.3V_6  [C0603]  142.15 84.68 270 bottom
C1010  10U/6.3_6  [C0603]  142.78 96.81 180 top
C1011  10U/6.3_6  [C0603]  143.57 84.68 270 bottom
C1012  1U/6.3V_4  [C0402]  145.8 100.26 0 top
C1013  1U/6.3V_4  [C0402]  140.91 109.45 0 top
C1014  1U/6.3V_4  [C0402]  140.91 110.47 0 top
C1015  1U/6.3V_4  [C0402]  145.8 98.88 0 top
C1016  1U/6.3V_4  [C0402]  145.28 108.05 0 top
C1017  1U/6.3V_4  [C0402]  147.45 109.21 270 top
C1018  1U/6.3V_4  [C0402]  151.75 80.2 270 top
C1019  1U/6.3V_4  [C0402]  153.05 79.97 270 bottom
C1020  1U/6.3V_4  [C0402]  151.01 79.97 270 bottom
C1021  1U/6.3V_4  [C0402]  152.06 79.98 270 bottom
C1022  1U/6.3V_4  [C0402]  134.12 100.17 180 top
C1023  1U/6.3V_4  [C0402]  153.61 73.61 90 top
C1024  1U/6.3V_4  [C0402]  153.62 78.13 270 top
C1025  22U/6.3V_6  [C0603]  165.67 82.1 180 bottom
C1026  22U/6.3V_6  [C0603]  165.67 80.68 180 bottom
C1027  1U/6.3V_4  [C0402]  132.11 139.96 270 top
C1028  1U/6.3V_4  [C0402]  152.36 125.38 180 top
C1029  1U/6.3V_4  [C0402]  178.76 112.31 270 top
C1030  1U/6.3V_4  [C0402]  164.26 90.08 270 top
C1031  1U/6.3V_4  [C0402]  129.44 126.76 180 top
C1032  1U/6.3V_4  [C0402]  150.07 139.86 270 top
C1033  1U/6.3V_4  [C0402]  164.02 114.57 180 top
C1034  1U/6.3V_4  [C0402]  178.6 91.6 0 top
C1035  1U/6.3V_4  [C0402]  123.89 134.98 90 top
C1036  1U/6.3V_4  [C0402]  156.51 136.53 180 top
C1037  1U/6.3V_4  [C0402]  172.26 121.14 90 bottom
C1038  1U/6.3V_4  [C0402]  171.9 83.16 270 bottom
C1039  10U/6.3_6  [C0603]  174.7 122.36 90 bottom
C1040  10U/6.3_6  [C0603]  176.07 84.88 0 top
C1041  0.1U/16V_4  [C0402]  148.27 137.9 0 top
C1042  0.1U/16V_4  [C0402]  138.46 136.79 270 top
C1043  0.1U/16V_4  [C0402]  145.94 138.66 180 top
C1044  0.1U/16V_4  [C0402]  175.37 113.42 90 top
C1045  0.1U/16V_4  [C0402]  164.89 95.29 180 top
C1046  0.1U/16V_4  [C0402]  174.44 98.91 0 top
C1047  0.1U/16V_4  [C0402]  130.33 129.93 270 top
C1048  0.1U/16V_4  [C0402]  146.9 129.82 0 top
C1049  0.1U/16V_4  [C0402]  176.84 113.81 0 top
C1050  0.1U/16V_4  [C0402]  168.07 90.47 180 top
C1051  0.1U/16V_4  [C0402]  138.46 138.57 270 top
C1052  0.1U/16V_4  [C0402]  152.1 130.08 270 top
C1053  0.1U/16V_4  [C0402]  173.04 105.52 0 top
C1054  0.1U/16V_4  [C0402]  165.78 98.59 0 top
C1055  0.1U/16V_4  [C0402]  125.25 137.93 90 top
C1056  0.1U/16V_4  [C0402]  138.46 134.63 270 top
C1057  0.1U/16V_4  [C0402]  155.26 133.84 270 top
C1058  0.1U/16V_4  [C0402]  175.07 105.52 0 top
C1059  0.1U/16V_4  [C0402]  176.71 90.47 0 top
C1060  0.1U/16V_4  [C0402]  168.08 105.55 0 top
C1061  1U/6.3V_4  [C0402]  127.22 135.49 180 top
C1062  1U/6.3V_4  [C0402]  156.8 132.49 270 top
C1063  1U/6.3V_4  [C0402]  173.29 115.71 270 top
C1064  1U/6.3V_4  [C0402]  176.31 96.65 270 top
C1065  1U/6.3V_4  [C0402]  168.54 83.16 270 bottom
C1066  1U/6.3V_4  [C0402]  172.39 98.72 0 top
C1067  1U/6.3V_4  [C0402]  176 121.95 270 bottom
C1068  1U/6.3V_4  [C0402]  141.72 138.54 270 bottom
C1069  1U/6.3V_4  [C0402]  134.4 129.42 270 top
C1070  10U/6.3_6  [C0603]  125.13 135.52 90 top
C1071  1U/6.3V_4  [C0402]  125.9 139.86 180 top
C1072  1U/6.3V_4  [C0402]  143.85 139.48 270 top
C1073  1U/6.3V_4  [C0402]  177.12 117.24 90 top
C1074  1U/6.3V_4  [C0402]  167.47 83.17 270 bottom
C1075  1U/6.3V_4  [C0402]  133.16 136.4 90 top
C1076  1U/6.3V_4  [C0402]  176.32 98.85 0 top
C1077  1U/6.3V_4  [C0402]  141.75 136.66 90 bottom
C1078  1U/6.3V_4  [C0402]  138.46 132.09 270 top
C1079  1U/6.3V_4  [C0402]  130.33 137.3 270 top
C1080  1U/6.3V_4  [C0402]  145.25 128.81 90 top
C1081  1U/6.3V_4  [C0402]  174.69 110.61 180 top
C1082  1U/6.3V_4  [C0402]  166.16 90.47 0 top
C1083  1U/6.3V_4  [C0402]  125.38 129.8 270 top
C1084  1U/6.3V_4  [C0402]  143.72 135.92 270 top
C1085  1U/6.3V_4  [C0402]  166.3 105.55 0 top
C1086  1U/6.3V_4  [C0402]  166.55 85.74 0 top
C1087  1U/6.3V_4  [C0402]  176.72 110.51 180 top
C1088  1U/6.3V_4  [C0402]  176.98 105.52 180 top
C1089  10U/6.3_6  [C0603]  123.23 139.73 90 top
C1090  1U/6.3V_4  [C0402]  151.96 138.03 90 top
C1091  1U/6.3V_4  [C0402]  176.59 118.63 180 top
C1092  1U/6.3V_4  [C0402]  178.99 86.15 180 top
C1093  1U/6.3V_4  [C0402]  140.61 138.53 270 bottom
C1094  1U/6.3V_4  [C0402]  173.55 85.07 90 top
C1095  1U/6.3V_4  [C0402]  172.4 85.07 90 top
C1096  1U/6.3V_4  [C0402]  143.85 137.72 270 top
C1097  1U/6.3V_4  [C0402]  140.62 136.64 90 bottom
C1098  1U/6.3V_4  [C0402]  132.82 138.33 0 top
C1099  0.1U/16V_4  [C0402]  64.7 121.68 270 bottom
C1100  0.1U/16V_4  [C0402]  65.67 121.68 270 bottom
C1103  0.01U/50V/X7R_4  [C0402]  181.42 18.9 0 bottom
C1104  0.01U/50V/X7R_4  [C0402]  181.42 17.76 0 bottom
C1105  0.01U/50V/X7R_4  [C0402]  181.42 21.19 0 bottom
C1106  0.01U/50V/X7R_4  [C0402]  181.42 20.05 0 bottom
C1107  22U/6.3V/X5R_6  [C0603]  69.89 99.83 0 top
C1108  47U/4V/X5R_6  [C0603]  77.2 101.91 90 top
C1109  22U/6.3V/X5R_6  [C0603]  78.03 110.06 0 top
C1110  22U/6.3V/X5R_6  [C0603]  72.41 98.22 0 top
C1111  47U/4V/X5R_6  [C0603]  77.66 106.91 180 top
C1112  22U/6.3V/X5R_6  [C0603]  71.25 110.74 90 top
C1113  22U/6.3V/X5R_6  [C0603]  75.03 98.22 180 top
C1114  22U/6.3V/X5R_6  [C0603]  67.47 113.9 0 top
C1115  22U/6.3V/X5R_6  [C0603]  64.24 118.14 180 top
C1116  22U/6.3V/X5R_6  [C0603]  64.24 113.9 180 top
C1117  22U/6.3V/X5R_6  [C0603]  60.11 112.16 90 top
C1118  22U/6.3V/X5R_6  [C0603]  56.11 112.31 0 top
C1119  22U/6.3V/X5R_6  [C0603]  55.88 102.09 0 top
C1120  22U/6.3V/X5R_6  [C0603]  67.47 115.31 0 top
C1121  22U/6.3V/X5R_6  [C0603]  60.74 118.14 0 top
C1122  22U/6.3V/X5R_6  [C0603]  72.77 113.16 90 top
C1123  22U/6.3V/X5R_6  [C0603]  74.19 113.16 90 top
C1125  47U/4V/X5R_6  [C0603]  77.2 104.68 270 top
C1126  22U/6.3V/X5R_6  [C0603]  56.66 109.2 180 top
C1127  22U/6.3V/X5R_6  [C0603]  56.66 107.23 180 top
C1131  22U/6.3V/X5R_6  [C0603]  59.14 108.97 270 top
C1132  1U/6.3V_4  [C0402]  252.16 11.16 270 bottom
C1133  4.7U/6.3V_6  [C0603]  247.59 17.66 270 bottom
C1134  0.1U/16V_4  [C0402]  248.91 17.25 90 bottom
C1135  1U/6.3V_4  [C0402]  249.21 19.89 180 bottom
C1138  0.1U/16V/X7R_4  [C0402]  262.95 52.05 180 top
C1139  0.1U/16V/X7R_4  [C0402]  262.95 53.07 180 top
C1140  0.1U/16V/X7R_4  [C0402]  268.32 50.7 180 top
C1141  0.1U/16V/X7R_4  [C0402]  268.32 51.74 180 top
C1142  0.1U/16V/X7R_4  [C0402]  262.95 54.21 180 top
C1143  0.1U/16V/X7R_4  [C0402]  262.95 55.22 180 top
C1144  0.1U/16V_4  [C0402]  269.3 52.81 0 bottom
C1175  0.1U/16V/X7R_4  [C0402]  217.79 12.27 0 top
C1176  0.1U/16V/X7R_4  [C0402]  227.75 28.81 90 top
C1177  0.1U/16V/X7R_4  [C0402]  217.82 13.34 180 top
C1178  0.1U/16V/X7R_4  [C0402]  238.95 22.59 0 top
C1181  0.1U/16V/X7R_4  [C0402]  214.92 11.08 0 top
C1182  0.1U/16V/X7R_4  [C0402]  215.74 24.29 180 top
C1183  1U/6.3V_4  [C0402]  221.86 15.85 90 bottom
C1188  *10P/50V_4_NC  [C0402]  233.69 27.54 0 bottom
C1190  0.1U/16V/X7R_4  [C0402]  216.35 20.55 0 top
C1191  0.1U/16V_4  [C0402]  257.11 20.93 90 bottom
C1192  4.7U/6.3V_6  [C0603]  258.33 20.93 90 bottom
C1200  47U/4V/X5R_6  [C0603]  81.04 100.07 90 top
C1202  47U/4V/X5R_6  [C0603]  79.41 103.56 0 top
C1206  47U/4V/X5R_6  [C0603]  78.03 108.64 0 top
C1209  22U/6.3V/X5R_6  [C0603]  81.57 98.05 180 top
C1210  0.1U/16V/X7R_4  [C0402]  239.03 16.24 90 top
C1211  1U/6.3V_4  [C0402]  223.03 28.81 90 top
C1212  0.1U/16V_4  [C0402]  24.6 22.64 0 bottom
C1213  0.1U/16V_4  [C0402]  24.6 21.65 0 bottom
C1214  0.1U/16V_4  [C0402]  26 17.56 0 bottom
C1215  0.1U/16V_4  [C0402]  26 16.52 0 bottom
C1216  0.1U/16V_4  [C0402]  25.98 19.52 0 bottom
C1217  0.1U/16V_4  [C0402]  25.98 18.53 0 bottom
C1218  0.1U/16V_4  [C0402]  25.99 12.48 0 bottom
C1219  0.1U/16V_4  [C0402]  26 13.45 0 bottom
C1220  0.1U/16V_4  [C0402]  16.14 17.61 0 bottom
C1221  0.1U/16V_4  [C0402]  16.14 18.75 0 bottom
C1222  0.1U/16V_4  [C0402]  16.14 11.84 0 bottom
C1223  0.1U/16V_4  [C0402]  16.14 12.91 0 bottom
C1225  0.1U/16V/X7R_4  [C0402]  18.52 14.75 90 bottom
C1227  0.1U/16V/X7R_4  [C0402]  18.75 21.06 270 bottom
C1230  1U/6.3V_4  [C0402]  249.24 18.75 180 bottom
C1231  1U/6.3V_4  [C0402]  140.86 131.81 270 top
C1232  1U/6.3V_4  [C0402]  161.84 123.02 270 bottom
C1236  *10P/50V_4_NC  [C0402]  258.1 15.23 270 bottom
C1237  0.1U/16V_4  [C0402]  263.49 53.95 270 bottom
C1238  *0.1U/16V_4_X7R_NC  [C0402]  126.82 28.07 90 bottom
C1239  *0.1U/16V_4_X7R_NC  [C0402]  155.64 36.05 90 bottom
C9362  *0.1U/16V_4_NC  [C0402]  137.05 28.81 270 bottom
C9363  *0.1U/16V_4_NC  [C0402]  14.06 12.2 270 bottom
C9364  *0.1U/16V_4_NC  [C0402]  128.46 45.57 0 bottom
C9365  *0.1U/16V_4_NC  [C0402]  126.84 44.1 270 top
C9366  *0.1U/16V/X7R_4_NC  [C0402]  241.75 21.32 90 top
C9367  *0.1U/16V_4_X7R_NC  [C0402]  150.33 40.35 0 bottom
C9368  *22U/6.3V_6_NC  [C0603]  194.48 31.28 0 bottom
C9369  *22U/6.3V_6_NC  [C0603]  194.68 10.83 0 bottom
C9370  0.1U/16V/X7R_4  [C0402]  24.73 7.22 270 top
C9371  *0.1U/16V_4_NC  [C0402]  123.12 80.62 90 bottom
C9372  *0.1U/16V_4_NC  [C0402]  124.41 77.94 0 bottom
C9373  0.1U/16V/X7R_4  [C0402]  131.22 85.46 90 bottom
C9374  0.1U/25V_4  [C0402]  141.23 17.36 180 bottom
C9375  0.1U/16V/X7R_4  [C0402]  121.06 14.83 180 bottom
C9376  0.1U/16V/X7R_4  [C0402]  55.88 26.01 270 top
C9377  *0.1U/16V/X7R_4_NC  [C0402]  117.79 112.5 0 top
C9378  *0.1U/16V/X7R_4_NC  [C0402]  115.13 110.47 180 top
C9379  2.2U/25V_4  [C0402]  85.41 56.88 270 top
C9380  2.2U/25V_4  [C0402]  82.11 44.73 90 top
C9381  2.2U/25V_4  [C0402]  83.12 44.73 90 top
C9382  0.1u/16V_4  [C0402]  81.47 57.51 180 top
C9383  2.2U/25V_4  [C0402]  84.39 56.88 270 top
C9384  4.7U/6.3V_4  [C0402]  155 77.83 180 top
C9385  *22U/6.3V_6_NC  [C0603]  166.18 81.39 180 top
C9386  *22U/6.3V_6_NC  [C0603]  167.32 78.34 180 top
C9387  *22U/6.3V_6_NC  [C0603]  166.69 79.86 180 top
C9388  *22U/6.3V_6_NC  [C0603]  171.64 82.53 0 top
C9389  0.1U/16V_4  [C0402]  39.1 116.95 90 bottom
C9390  0.1U/16V_4  [C0402]  147.56 26.65 90 bottom
C9391  0.1U/16V_4  [C0402]  152.82 33.18 0 bottom
C9392  0.1U/16V_4  [C0402]  154.75 35.29 0 top
C9393  0.1U/16V_4  [C0402]  170.5 42.52 180 top
C9394  0.1U/16V_4  [C0402]  120.59 143.11 90 top
C9395  0.1U/16V_4  [C0402]  42.86 100.82 90 bottom
C9396  0.1U/25V_4  [C0402]  7.94 25.89 0 bottom
C9397  0.1U/25V_4  [C0402]  19.24 30.84 180 top
C9398  0.1U/25V_4  [C0402]  21.02 3.79 270 bottom
C9399  0.1U/25V_4  [C0402]  22.04 58.15 90 bottom
C9400  0.1U/25V_4  [C0402]  92.14 144 270 bottom
C9401  0.1U/25V_4  [C0402]  93.28 144 270 bottom
C9402  0.1U/25V_4  [C0402]  156.91 54.59 180 bottom
C9403  0.1U/25V_4  [C0402]  157.29 56.11 90 bottom
C9404  0.1U/25V_4  [C0402]  46.29 130.03 270 bottom
C9405  0.1U/25V_4  [C0402]  41.97 112.12 180 top
CN1  50281-00401-001_Header  [50281-00401-001-4P-L]  33.79 124.67 90 top
CN2  196451-30041-3  [51643-03001-V01-30P-L]  26.4 50.13 270 top
CN3  DFHD08MR215  [88266-080L-8P-L]  8.25 36.42 270 top
CN4  50503-0080N-001  [50503-0080N-001-8P-L]  168 32.05 0 top
CN5  50473-0400M-V01  [LVDS-50473-0400M-V01-40P-L]  19.2 14.55 270 top
CN6  C100MP-10809-L  [RJ45-C100MP-10809-L-8P]  282.05 99.9 270 bottom
CN7  80146-1021  [HDMI-59058-0190D-001-19P]  287.5 76.68 270 bottom
CN8  YUSB0012-P001A  [USB-YUSB0012-P001A-10P]  286.45 52.55 270 bottom
CN9  GS12401-1011P-7H  [GS12401-1011-40P-R-NH-SMT]  177.35 47.78 180 bottom
CN10  APCI0162-P001A  [NGFF-APCI0162-P001A-75P-KA]  4.1 11.93 90 bottom
CN11  TU1502WNV-08SA-NL-A  [50293-0087N-002-8P-LDV_AB]  44.37 9.65 270 bottom
CN12  CVS520EM1RB-NH  [GS12201-1011-9F-20P-L-SMT]  31.67 5.3 0 bottom
CN13  *HDT_NC  [ASP-137098-05-20P-LDV]  44.13 23.47 270 top
CN16  DDR4-4mm  [DDR4-ADDR0106-P005A-STD-SMT]  72.6 48.98 0 bottom
CN17  DDR4-8mm  [DDR4-ADDR0069-P009A-STD-SMT]  72.6 61.55 0 bottom
CON1  NASM0-S6701-TS85  [NGFF-NASM0-S6701-TS85-KM-SMT]  189.2 20.92 270 bottom
CS1  0.1U/16V/X7R_4  [C0402]  68.24 118.34 180 top
CS2  0.1U/16V/X7R_4  [C0402]  89.32 117.88 180 top
CS3  0.1U/16V/X7R_4  [C0402]  81.22 26.08 180 top
CS4  0.1U/16V/X7R_4  [C0402]  110.45 105.54 90 bottom
CS6  0.1U/25V_4  [C0402]  183.54 33.21 0 bottom
CS8  0.1U/16V/X7R_4  [C0402]  69.66 117.95 270 top
D1  RB500V-40  [DSM]  280.73 66.04 0 top
D2  RB500V-40  [DSM]  280.73 64.01 0 top
D3  BAT54CW  [SOT323_213-2_1-1_3-2N7002W]  175.84 50.6 180 top
D4  BAT54CW  [SOT323_213-2_1-1_3-2N7002W]  177.48 48.11 180 top
D5  BAT54CW  [SOT323_213-2_1-1_3-2N7002W]  177.48 45.57 180 top
D6  RB500V-40  [DSM]  166.82 38.59 90 top
D15  BAT54CW  [SOT323_213-2_1-1_3-2N7002W]  227.9 19.97 0 bottom
D16  BAT54CW  [SOT323_213-2_1-1_3-2N7002W]  227.54 13.75 180 bottom
D17  RB500V-40  [DSM]  39.05 95.86 90 bottom
D18  RB500V-40  [DSM]  40.96 95.86 90 bottom
D19  RB500V-40  [DSM]  102.65 111.71 180 top
D21  RB500V-40  [DSM]  84.77 125.74 90 bottom
D22  *RB500V-40_NC  [DSM]  83 125.74 90 bottom
D23  RB500V-40  [DSM]  86.55 125.74 90 bottom
D28  RB500V-40  [DSM]  216.6 19.16 180 top
D29  RB500V-40  [DSM]  216.62 14.89 180 top
D30  RB500V-40  [DSM]  214.69 22.89 180 top
D42  RB500V-40  [DSM]  240.42 18.88 0 top
D43  RB500V-40  [DSM]  216.6 16.74 0 top
D46  RB500V-40  [DSM]  217.59 28.8 180 top
D50  *RB500V-40_NC  [DSM]  28.51 42.57 180 bottom
D52  *RB500V-40_NC  [DSM]  28.51 44.5 180 bottom
EC11  *6.8P/50V/NPO_4_NC  [C0402]  267.4 108.01 90 top
EC12  *6.8P/50V/NPO_4_NC  [C0402]  267.4 106.29 270 top
EC13  *6.8P/50V/NPO_4_NC  [C0402]  267.4 103.61 90 top
EC14  *6.8P/50V/NPO_4_NC  [C0402]  267.4 101.58 270 top
EC15  *6.8P/50V/NPO_4_NC  [C0402]  268.42 99.55 90 top
EC16  *6.8P/50V/NPO_4_NC  [C0402]  268.42 97.52 270 top
EC17  *6.8P/50V/NPO_4_NC  [C0402]  267.4 95.48 90 top
EC18  *6.8P/50V/NPO_4_NC  [C0402]  268.42 93.45 270 top
EC20  100P/50V_4  [C0402]  274.29 56.88 90 top
EC24  *10P/50V_4_NC  [C0402]  164.05 35.67 270 top
EC25  *10P/50V_4_NC  [C0402]  165.19 35.67 270 top
EC26  *10P/50V_4_NC  [C0402]  123.89 149.59 180 top
EC28  *10P/50V_4_NC  [C0402]  26.01 17.12 0 top
EC29  0.1U/25V_6  [C0603]  108.7 12.71 90 top
EC30  1000P/50V_4  [C0402]  110.1 12.68 90 top
EC31  2200P/50V_4  [C0402]  111.21 12.68 90 top
EC32  *10P/50V_4_NC  [C0402]  24.73 10.97 90 top
EC33  *10P/50V_4_NC  [C0402]  24.73 9.18 270 top
EC34  2200P/50V_4  [C0402]  139.64 8.23 90 top
EC35  0.1U/25V_6  [C0603]  140.91 8.23 90 top
EC36  0.1U/25V_6  [C0603]  47 8.06 270 top
EC37  1000P/50V_4  [C0402]  48.25 8.01 270 top
EC38  2200P/50V_4  [C0402]  49.37 8.01 270 top
EC42  *100P/50V_4_NC  [C0402]  15.56 37.06 180 top
EC43  *100P/50V_4_NC  [C0402]  15.56 38.29 180 top
EC44  *100P/50V_4_NC  [C0402]  16.46 43.02 180 top
EC45  *100P/50V_4_NC  [C0402]  13.14 43.02 0 top
EC54  100P/50V_4  [C0402]  34.48 60.89 180 top
EC55  100P/50V_4  [C0402]  34.48 59.87 180 top
EC56  100P/50V_4  [C0402]  34.48 58.78 180 top
EC57  100P/50V_4  [C0402]  34.48 57.55 180 top
EC59  100P/50V_4  [C0402]  34.48 56.59 180 top
EC60  100P/50V_4  [C0402]  34.48 55.63 180 top
EC61  100P/50V_4  [C0402]  34.48 54.62 180 top
EC62  100P/50V_4  [C0402]  34.48 53.6 180 top
EC63  *10P/50V_4_NC  [C0402]  169.1 54.08 90 bottom
EC64  *10P/50V_4_NC  [C0402]  170.24 54.08 90 bottom
EC65  100P/50V_4  [C0402]  34.48 52.58 180 top
EC66  100P/50V_4  [C0402]  34.48 51.57 180 top
EC67  100P/50V_4  [C0402]  34.48 50.55 180 top
EC68  100P/50V_4  [C0402]  34.48 49.54 180 top
EC69  100P/50V_4  [C0402]  34.48 48.52 180 top
EC70  100P/50V_4  [C0402]  34.48 47.5 180 top
EC71  100P/50V_4  [C0402]  34.48 46.49 180 top
EC72  100P/50V_4  [C0402]  34.48 45.47 180 top
EC73  100P/50V_4  [C0402]  34.48 44.38 180 top
EC74  100P/50V_4  [C0402]  34.48 43.29 180 top
EC75  100P/50V_4  [C0402]  34.48 42.19 180 top
EC76  100P/50V_4  [C0402]  34.48 41.05 180 top
EC77  100P/50V_4  [C0402]  34.48 39.91 180 top
EC78  100P/50V_4  [C0402]  34.48 38.78 180 top
EC79  100P/50V_4  [C0402]  34.48 35.36 180 top
EC80  100P/50V_4  [C0402]  34.48 37.65 180 top
EC81  100P/50V_4  [C0402]  34.48 36.52 180 top
EC87  2200P/50V_4  [C0402]  83.48 12.2 270 bottom
EC88  0.1U/25V_6  [C0603]  159.07 7.98 90 bottom
EC89  2200P/50V_4  [C0402]  160.39 7.63 90 bottom
EC90  15P/50V_4  [C0402]  87.69 116.31 0 top
EC91  *10P/50V_4_NC  [C0402]  123.89 148.57 0 top
EC139  0.1U/25V_4  [C0402]  102.44 142.96 90 top
EC140  2200P/50V_4  [C0402]  103.52 142.92 90 top
EC141  2200P/50V_4  [C0402]  77.96 143.03 90 top
EC142  0.1U/25V_4  [C0402]  77 143.03 90 top
EC143  2200P/50V_4  [C0402]  87.01 142.33 90 top
EC144  0.1U/25V_4  [C0402]  85.98 142.3 90 top
EC145  2200P/50V_4  [C0402]  69.4 142.58 90 top
EC146  0.1U/25V_4  [C0402]  70.56 142.58 90 top
EC147  0.1U/25V_4  [C0402]  61.61 141.8 90 top
EC148  2200P/50V_4  [C0402]  60.51 141.8 90 top
EC151  2200P/50V_4  [C0402]  147.21 33.13 270 bottom
EC152  2200P/50V_4  [C0402]  17.89 34.47 90 top
EC153  0.1U/25V_6  [C0603]  16.71 34.14 90 top
EC154  2200P/50V_4  [C0402]  157.98 63.91 0 top
EC155  0.1U/25V_4  [C0402]  157.98 64.92 0 top
EC156  2200P/50V_4  [C0402]  143.09 59.83 270 top
EC157  0.1U/25V_4  [C0402]  144.11 59.83 270 top
EC158  2200P/50V_4  [C0402]  134.84 59.83 270 top
EC159  0.1U/25V_4  [C0402]  135.86 59.83 270 top
EC160  2200P/50V_4  [C0402]  166.91 59.82 90 top
EC161  2200P/50V_4  [C0402]  40.4 107.88 180 bottom
EC162  100P/50V_4  [C0402]  249.17 22.83 270 top
EC163  100P/50V_4  [C0402]  246.44 25.38 180 top
EC164  100P/50V_4  [C0402]  200.34 21.82 270 top
EC165  100P/50V_4  [C0402]  208.73 30.21 270 top
EC166  100P/50V_4  [C0402]  197.63 24.87 180 top
EL3  DLP11SN900HL2L  [CHOKE-DLP11SN900HL2L-4P-1]  269.1 49.41 0 top
EL14  FCM1005KF-102T03(1000 300MA)  [R0402]  51.14 10.41 180 bottom
ESD1  *TVL ST23 04 AD0_NC  [TSOP6-2_8-95]  114.54 13.64 90 bottom
EU1  AZ1045-04F  [UDFN10-2_5X1-5]  272.48 53.87 90 top
FAN1  50278-00401-001  [50278-00401-001-4P-L]  34.28 85.32 0 top
FAN2  50278-00401-001  [50278-00401-001-4P-L]  172.52 71.82 0 top
FL1  HCB2012KF800T50(80,5A)  [R0805]  51.47 7.4 180 bottom
FL2  HCB2012KF800T50(80,5A)  [R0805]  51.47 5.36 180 bottom
FS1  1206L050YR  [FSMD1206P150TS]  106.49 33.13 90 top
H1  *H-C315D94P2_NC  [H-C315D94P2]  56.35 149 0 top
H2  *H-C315D94P2_NC  [H-C315D94P2]  148.35 149 0 top
H3  *h-tc256bc150d150pt_NC  [H-TC256BC150D150PT]  51.45 129.9 0 top
H4  *h-tc256bc150d150pt_NC  [H-TC256BC150D150PT]  93.45 129.9 0 top
H5  *h-tc256bc150d150pt_NC  [H-TC256BC150D150PT]  119.35 128.65 0 top
H6  *h-tc256bc150d150pt_NC  [H-TC256BC150D150PT]  161.35 128.65 0 top
H7  *h-c236o83x126p2_NC  [H-C236O83X126P2]  285.06 112.7 180 top
H8  *h-tc256bc150d150pt_NC  [H-TC256BC150D150PT]  51.45 76.9 0 top
H9  *h-tc256bc150d150pt_NC  [H-TC256BC150D150PT]  93.45 76.9 0 top
H10  *h-tc256bc150d150pt_NC  [H-TC256BC150D150PT]  119.35 75.65 0 top
H11  *h-tc256bc150d150pt_NC  [H-TC256BC150D150PT]  161.35 75.65 0 top
H12  *h-c303d197p2_NC  [H-C303D197P2]  6.35 50.5 0 top
H13  *h-c303d197p2_NC  [H-C303D197P2]  197.8 48.1 0 top
H16  *O-AM9-3_NC  [O-AM9-3]  96.45 3.75 0 top
H17  *H-C315I134D94P2_NC  [O-AM9-3]  182.55 3.75 0 top
H18  *H-C315I134D94P2_NC  [O-AM9-3]  258.45 3.74 0 top
H19  *h-c157d83p2_NC  [H-C157D83P2]  285.05 4.05 0 top
H20  *H-O83X126D83X126N_NC  [H-O83X126D83X126N]  13.4 4.05 90 top
HDMIF1  0805L150ULYR  [F2_1X1_35-2_2-0_75H]  279.72 64.75 90 bottom
J1  51678-00401-V01  [51575-00401-V01-4P-L]  103.95 41.33 180 top
J2  50505-00401-V01  [50505-00401-V01-4P-L]  248.3 30.4 180 top
J3  50506-00641-V01  [50506-00601-V01-6P-L]  204.15 27.74 0 top
JBAT1  50288-01171-V01  [50288-01171-V01-11P-L]  116.1 4.6 180 bottom
JCARD1  PSDBR2-09GLBS1NN4H0  [SDCARD-PSDBR2-09GLBS1NN4H0-11P]  268.05 22.7 270 bottom
JP51  *SP_NC  [SOLDERJUMPER-2]  88.45 54.81 90 top
L14  FCM1005KF-121T05  [R0402]  241.11 15.6 180 top
L15  FCM1005KF-121T05  [R0402]  241.11 16.74 180 top
NOREF  -  []  204.41 -52.85 0 top
NOREF#2  -  []  80.48 39.94 0 top
NOREF#3  -  []  89.21 26.36 0 top
NOREF#4  -  [unnamed#2]  5.68 6.81 0 top
NOREF#5  -  []  251.65 13.06 0 top
NOREF#6  -  []  67.88 40.24 0 top
NOREF#7  -  []  153.61 -92.98 0 top
NOREF#8  -  [unnamed#2]  38.34 127.97 0 top
NOREF#9  -  [unnamed#2]  279.97 114.05 0 top
NOREF#10  -  [unnamed#2]  17.95 4.78 180 bottom
NOREF#11  -  [unnamed#2]  30.14 128.64 180 bottom
NOREF#12  -  []  7.63 32.29 180 bottom
NOREF#13  -  [unnamed#2]  279.72 114.03 180 bottom
NOREF#14  -  []  251.14 26.06 180 bottom
PAD1  *spad-am9c-1_NC  [SPAD-AM9C-1]  33.1 25.65 0 top
PAD2  *spad-am9c-1_NC  [SPAD-AM9C-1]  33.1 25.65 180 bottom
PC79  0.1U/25V_4  [C0402]  73.71 16.26 270 bottom
PC81  0.1U/25V_4  [C0402]  75.28 16.96 180 bottom
PC82  0.1U/25V_4  [C0402]  75.31 15.47 180 bottom
PC83  *2200P/50V_4_NC  [C0402]  136.28 8.13 90 top
PC84  1000P/50V_4  [C0402]  56.71 8.82 270 top
PC85  0.047U/25V_4  [C0402]  57.82 8.82 270 top
PC86  0.1U/25V_6  [C0603]  148.3 17.15 270 bottom
PC87  0.1U/25V_6  [C0603]  145.15 6.18 90 bottom
PC88  2.2U/25V_4  [C0402]  60.64 6.8 270 top
PC89  0.1U/25V_6  [C0603]  144.39 13.7 270 bottom
PC90  0.1U/25V_6  [C0603]  143.42 11.61 0 bottom
PC138  *0.01U/50V_4_NC  [C0402]  24.5 43.03 270 bottom
PC142  1U/6.3V_4  [C0402]  24.14 44.94 90 bottom
PC144  0.1U/25V_4  [C0402]  20.77 44.94 270 bottom
PC147  33N/10V_4  [C0402]  18.61 44.94 270 bottom
PC151  *150P/25V_4_NC  [C0402]  19.62 44.94 270 bottom
PC188  4700P/25V_4  [C0402]  34.99 78.03 180 bottom
PC191  0.1U/16V_4  [C0402]  37.46 85.55 270 bottom
PC221  0.1U/16V_4  [C0402]  165.48 19.45 270 bottom
PC222  220U/6.3V/E25_7343  [CC7343]  133.16 15.47 0 bottom
PC223  150U/6.3V/E25_3528  [C3528]  164.66 15.35 0 bottom
PC224  100P/50V_4  [C0402]  75.12 13.98 270 bottom
PC225  1U/6.3V_4  [C0402]  150.03 13.85 270 bottom
PC226  2.2U/10V_6  [C0603]  74.82 12.27 180 bottom
PC227  10U/25V_8  [C0805]  108.73 12.65 270 bottom
PC228  10U/25V_8  [C0805]  110.81 12.65 270 bottom
PC229  100P/50V_4  [C0402]  51.14 11.37 0 bottom
PC230  0.1U/25V_6  [C0603]  82.21 12.27 270 bottom
PC231  10U/25V_8  [C0805]  78.35 12.2 270 bottom
PC232  10U/25V_8  [C0805]  80.4 12.2 270 bottom
PC233  10U/6.3V_6  [C0603]  125.72 11.03 0 bottom
PC234  0.1U/25V_6  [C0603]  153.86 11.31 180 bottom
PC235  0.1U/25V_6  [C0603]  146.6 9.38 270 bottom
PC236  0.047U/25V_4  [C0402]  74.36 9.67 0 bottom
PC237  0.1U/16V_4  [C0402]  125.84 9.83 0 bottom
PC238  100P/50V_4  [C0402]  66 10.27 0 bottom
PC239  0.1U/25V_6  [C0603]  51.68 9.2 0 bottom
PC240  10U/25V_8  [C0805]  157.16 7.98 90 bottom
PC241  0.1U/25V_4  [C0402]  71.56 7.82 180 bottom
PC242  2200P/50V_4  [C0402]  89.85 8.16 180 bottom
PC243  10U/25V_8  [C0805]  139.71 8.11 90 bottom
PC244  10U/25V_8  [C0805]  141.69 8.11 90 bottom
PC245  1U/25V_6  [C0603]  73.14 7.85 90 bottom
PC246  0.01U/50V_4  [C0402]  68.59 7.96 90 bottom
PC247  0.1U/25V_6  [C0603]  150.76 6.79 90 bottom
PC248  1U/6.3V_4  [C0402]  149.21 7.02 90 bottom
PC249  *2200P/50V_4_NC  [C0402]  175.45 8.87 270 bottom
PC250  0.1U/25V_4  [C0402]  72.78 5.97 180 bottom
PC251  1U/25V_6  [C0603]  70.47 6.18 0 bottom
PC252  0.1U/25V_6  [C0603]  146.06 11.61 0 bottom
PC253  4.7U/6.3V_6  [C0603]  60.31 14.81 180 top
PC9092  *15U/25V/E100_3528_NC  [C3528]  159.53 12.55 270 bottom
PC9093  *15U/25V/E100_3528_NC  [C3528]  139.76 14.25 270 bottom
